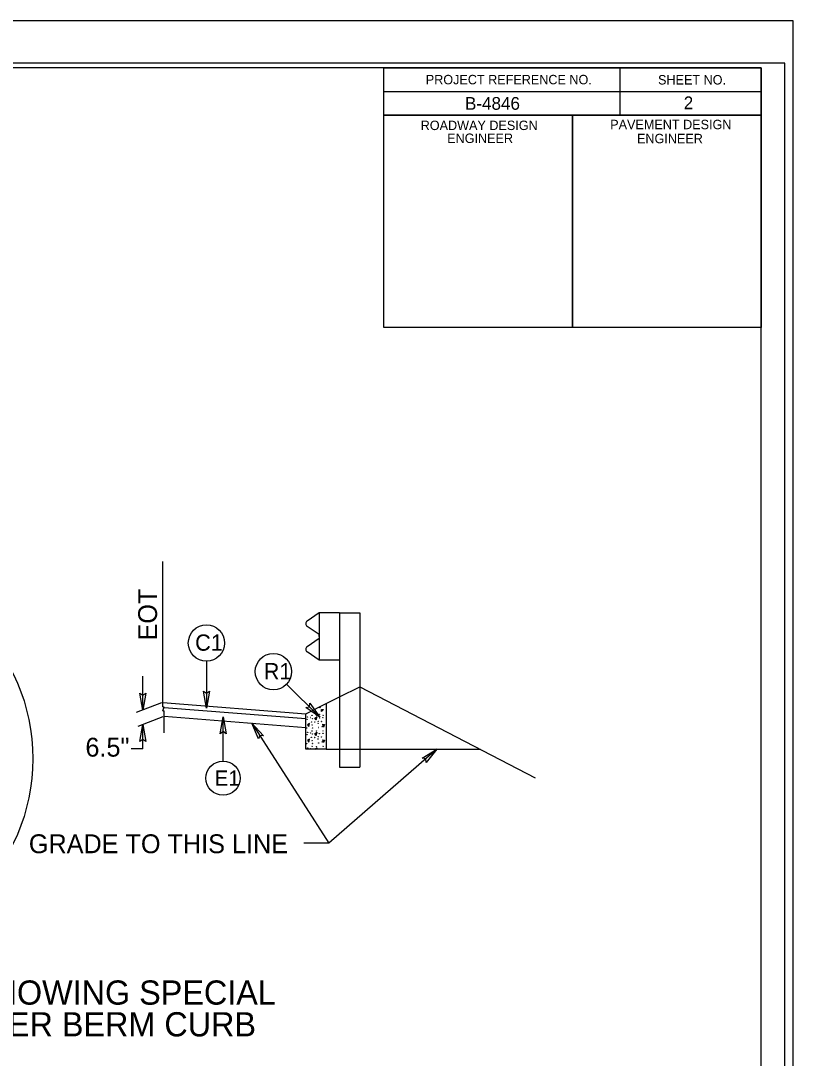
# Model space of a CAD drawing. Extents: x 1542177 to 1542464, y 45134 to 45344.
# Drawn here: x 1542327.96 to 1542360.73, y 45284.62 to 45328.62 of the extents above; entities that cross this region are included whole.
import ezdxf

# ---------------------------------------------------------------- set-up
doc = ezdxf.new("R2010")
doc.units = 0
for name, color, linetype in [('Default', 7, 'Continuous'), ('Old_Level_1', 7, 'Continuous'), ('Old_Level_2', 7, 'Continuous'), ('Sheet Cutting Line CELL', 7, 'Continuous'), ('Sheet Data Field CELL', 7, 'Continuous'), ('Sheet Plot Border Inside CELL', 7, 'Continuous'), ('Sheet Plot Border Outside CELL', 7, 'Continuous'), ('Sheet Typical CELL', 7, 'Continuous'), ('Typical Curb CELL', 7, 'Continuous'), ('Typical Guardrail CELL', 7, 'Continuous'), ('Typical ID Circle CELL', 7, 'Continuous'), ('Typical Terminator CELL', 7, 'Continuous'), ('Typical Text ID Circle CELL', 7, 'Continuous')]:
    doc.layers.add(name, color=color, linetype=linetype)

msp = doc.modelspace()

# ---------------------------------------------------------------- linework, layer by layer
at = {"layer": 'Default'}
for p, q in [((1542333.987, 45299.521), (1542333.987, 45305.678)), ((1542333.133, 45299.378), (1542333.133, 45300.813)), ((1542342.338, 45300.372), (1542349.785, 45296.513)), ((1542333.928, 45299.687), (1542332.859, 45299.272)), ((1542333.987, 45299.71), (1542340.051, 45299.229)), ((1542333.987, 45299.521), (1542334.045, 45299.521)), ((1542333.987, 45299.35), (1542334.045, 45299.521)), ((1542333.987, 45299.35), (1542334.045, 45299.35)), ((1542334.037, 45299.498), (1542340.051, 45299.021)), ((1542334.045, 45298.421), (1542334.045, 45299.35)), ((1542333.986, 45299.1), (1542332.917, 45298.684)), ((1542334.045, 45299.123), (1542340.051, 45298.646)), ((1542333.133, 45297.738), (1542333.133, 45298.768)), ((1542333.133, 45297.738), (1542332.644, 45297.738)), ((1542340.914, 45297.718), (1542347.46, 45297.718))]:
    msp.add_line(p, q, dxfattribs=at)
for points in [[(1542333.257, 45300.098), (1542333.133, 45299.378), (1542333.005, 45300.102), (1542333.133, 45300.01)], [(1542333.009, 45298.048), (1542333.133, 45298.768), (1542333.261, 45298.044), (1542333.133, 45298.136)]]:
    msp.add_lwpolyline(points, close=True, dxfattribs=at)
at = {"layer": 'Old_Level_2'}
for points in [[(1542337.754, 45298.828), (1542341.027, 45293.738), (1542339.965, 45293.737)], [(1542345.609, 45297.718), (1542341.027, 45293.738), (1542339.965, 45293.737)]]:
    msp.add_lwpolyline(points, dxfattribs=at)
at = {"layer": 'Sheet Cutting Line CELL'}
msp.add_line((1542360.727, 45328.616), (1542226.007, 45328.616), dxfattribs=at)
at = {"layer": 'Sheet Plot Border Inside CELL'}
msp.add_lwpolyline([(1542360.367, 45326.82), (1542227.047, 45326.82), (1542227.047, 45242.412), (1542360.367, 45242.412)], close=True, dxfattribs=at)
at = {"layer": 'Sheet Plot Border Outside CELL'}
for points in [[(1542360.727, 45328.616), (1542226.007, 45328.616), (1542226.007, 45240.616), (1542360.727, 45240.616)], [(1542360.727, 45328.615), (1542226.007, 45328.615), (1542226.007, 45240.616), (1542360.727, 45240.616)]]:
    msp.add_lwpolyline(points, close=True, dxfattribs=at)
at = {"layer": 'Sheet Typical CELL'}
for p, q in [((1542353.367, 45326.612), (1542353.367, 45324.612)), ((1542343.363, 45325.612), (1542359.367, 45325.612)), ((1542351.367, 45324.612), (1542351.367, 45315.616))]:
    msp.add_line(p, q, dxfattribs=at)
for points in [[(1542359.367, 45326.616), (1542239.367, 45326.616), (1542239.367, 45242.616), (1542359.367, 45242.616)], [(1542343.363, 45326.616), (1542359.367, 45326.616), (1542359.367, 45324.612), (1542343.363, 45324.612)], [(1542343.363, 45324.612), (1542351.367, 45324.612), (1542351.367, 45315.612), (1542343.363, 45315.612)], [(1542351.367, 45324.612), (1542359.367, 45324.612), (1542359.367, 45315.612), (1542351.367, 45315.612)]]:
    msp.add_lwpolyline(points, close=True, dxfattribs=at)
at = {"layer": 'Typical Curb CELL'}
for p, q in [((1542341.475, 45299.94), (1542342.338, 45300.372)), ((1542340.914, 45299.66), (1542341.475, 45299.94)), ((1542340.051, 45299.229), (1542340.914, 45299.66)), ((1542340.711, 45299.401), (1542340.797, 45299.401)), ((1542340.716, 45299.315), (1542340.711, 45299.401)), ((1542340.797, 45299.401), (1542340.716, 45299.315)), ((1542340.914, 45299.66), (1542340.914, 45297.718)), ((1542340.051, 45297.718), (1542340.051, 45299.229)), ((1542340.431, 45299.04), (1542340.513, 45299.099)), ((1542340.472, 45298.949), (1542340.431, 45299.04)), ((1542340.513, 45299.099), (1542340.472, 45298.949)), ((1542340.206, 45298.81), (1542340.116, 45298.76)), ((1542340.116, 45298.76), (1542340.174, 45298.679)), ((1542340.174, 45298.679), (1542340.206, 45298.81)), ((1542340.771, 45298.783), (1542340.843, 45298.769)), ((1542340.806, 45298.66), (1542340.771, 45298.783)), ((1542340.843, 45298.769), (1542340.806, 45298.66)), ((1542340.206, 45298.15), (1542340.116, 45298.1)), ((1542340.116, 45298.1), (1542340.174, 45298.019)), ((1542340.174, 45298.019), (1542340.206, 45298.15)), ((1542340.431, 45298.38), (1542340.513, 45298.439)), ((1542340.472, 45298.289), (1542340.431, 45298.38)), ((1542340.513, 45298.439), (1542340.472, 45298.289)), ((1542340.771, 45298.123), (1542340.843, 45298.109)), ((1542340.806, 45298), (1542340.771, 45298.123)), ((1542340.843, 45298.109), (1542340.806, 45298)), ((1542340.914, 45297.718), (1542340.051, 45297.718)), ((1542340.431, 45297.72), (1542340.513, 45297.779)), ((1542340.432, 45297.718), (1542340.431, 45297.72)), ((1542340.513, 45297.779), (1542340.496, 45297.718))]:
    msp.add_line(p, q, dxfattribs=at)
for centre in [(1542340.296, 45299.32), (1542340.648, 45299.487), (1542340.102, 45298.995), (1542340.124, 45299.094), (1542340.246, 45299.067), (1542340.287, 45298.882), (1542340.314, 45299.158), (1542340.336, 45299.022), (1542340.431, 45299.298), (1542340.431, 45298.878), (1542340.504, 45299.153), (1542340.58, 45298.909), (1542340.621, 45299.203), (1542340.626, 45299.04), (1542340.716, 45298.896), (1542340.775, 45299.054), (1542340.784, 45299.162), (1542340.088, 45298.62), (1542340.124, 45298.434), (1542340.314, 45298.498), (1542340.318, 45298.747), (1542340.332, 45298.625), (1542340.504, 45298.493), (1542340.567, 45298.814), (1542340.594, 45298.643), (1542340.739, 45298.683), (1542340.784, 45298.502), (1542340.102, 45298.335), (1542340.246, 45298.407), (1542340.287, 45298.222), (1542340.318, 45298.086), (1542340.336, 45298.362), (1542340.431, 45298.217), (1542340.567, 45298.154), (1542340.58, 45298.249), (1542340.626, 45298.38), (1542340.716, 45298.236), (1542340.739, 45298.023), (1542340.775, 45298.394), (1542340.088, 45297.96), (1542340.124, 45297.774), (1542340.246, 45297.747), (1542340.314, 45297.838), (1542340.332, 45297.965), (1542340.504, 45297.833), (1542340.594, 45297.982), (1542340.775, 45297.734), (1542340.784, 45297.842)]:
    msp.add_circle(centre, 0.00635, dxfattribs=at)
at = {"layer": 'Typical Guardrail CELL'}
for p, q in [((1542340.611, 45303.507), (1542340.109, 45303.154)), ((1542341.475, 45303.507), (1542340.611, 45303.507)), ((1542340.611, 45303.507), (1542340.611, 45301.494)), ((1542341.475, 45303.507), (1542341.475, 45299.94)), ((1542341.475, 45303.507), (1542342.338, 45303.507)), ((1542342.338, 45303.507), (1542342.338, 45300.372)), ((1542340.611, 45302.581), (1542340.109, 45302.933)), ((1542340.611, 45302.419), (1542340.109, 45302.067)), ((1542340.611, 45302.5), (1542340.611, 45302.581)), ((1542340.611, 45302.5), (1542340.611, 45302.419)), ((1542340.611, 45301.494), (1542340.109, 45301.846)), ((1542341.475, 45301.494), (1542340.611, 45301.494)), ((1542342.338, 45300.372), (1542342.338, 45296.967)), ((1542341.475, 45299.94), (1542341.475, 45296.967)), ((1542341.475, 45296.967), (1542342.338, 45296.967))]:
    msp.add_line(p, q, dxfattribs=at)
for centre, start, end in [((1542340.186, 45303.044), 125.003, 235.0112), ((1542340.186, 45301.956), 125.0059, 235.0366)]:
    msp.add_arc(centre, 0.135, start, end, dxfattribs=at)
at = {"layer": 'Typical ID Circle CELL'}
for p, q in [((1542335.834, 45301.455), (1542335.834, 45299.467)), ((1542339.224, 45300.475), (1542340.648, 45299.087)), ((1542336.538, 45297.219), (1542336.538, 45299.093))]:
    msp.add_line(p, q, dxfattribs=at)
for centre, radius in [((1542320.225, 45297.318), 8.241), ((1542335.834, 45302.225), 0.769), ((1542338.674, 45301.012), 0.769), ((1542336.538, 45296.494), 0.725)]:
    msp.add_circle(centre, radius, dxfattribs=at)
at = {"layer": 'Typical Terminator CELL'}
for points in [[(1542335.957, 45300.179), (1542335.834, 45299.467), (1542335.708, 45300.183), (1542335.834, 45300.092)], [(1542340.223, 45299.672), (1542340.648, 45299.087), (1542340.046, 45299.496), (1542340.2, 45299.523)], [(1542336.416, 45298.38), (1542336.538, 45299.093), (1542336.665, 45298.376), (1542336.538, 45298.467)], [(1542338.036, 45298.163), (1542337.754, 45298.828), (1542338.248, 45298.294), (1542338.092, 45298.302)], [(1542344.991, 45297.344), (1542345.609, 45297.718), (1542345.151, 45297.153), (1542345.137, 45297.308)]]:
    msp.add_lwpolyline(points, close=True, dxfattribs=at)

# ---------------------------------------------------------------- texts
at = {"layer": 'Default'}
msp.add_text('EOT', height=0.8, rotation=90, dxfattribs=at).set_placement((1542333.739, 45302.332))
for s, height, p in [('6.5"', 0.8, (1542330.701, 45297.408)), ('DETAIL SHOWING SPECIAL', 1.02627, (1542320.704, 45286.889)), ('SHOULDER BERM CURB', 1.02627, (1542321.695, 45285.543))]:
    msp.add_text(s, height=height, dxfattribs=at).set_placement(p)
at = {"layer": 'Old_Level_1'}
msp.add_text('GRADE TO THIS LINE ', height=0.8, dxfattribs=at).set_placement((1542328.3, 45293.312))
at = {"layer": 'Sheet Data Field CELL'}
for s, p in [('B-4846', (1542346.804, 45324.84)), ('2', (1542356.081, 45324.864))]:
    msp.add_text(s, height=0.54, dxfattribs=at).set_placement(p)
at = {"layer": 'Sheet Typical CELL'}
for s, height, p in [('PROJECT REFERENCE NO.', 0.40001, (1542345.139, 45325.92)), ('SHEET NO.', 0.4, (1542354.991, 45325.912)), ('PAVEMENT DESIGN', 0.40001, (1542352.963, 45324.016)), ('ROADWAY DESIGN', 0.40001, (1542344.923, 45323.98)), ('ENGINEER', 0.4, (1542346.047, 45323.432)), ('ENGINEER', 0.4, (1542354.099, 45323.42))]:
    msp.add_text(s, height=height, dxfattribs=at).set_placement(p)
at = {"layer": 'Typical Text ID Circle CELL'}
for s, height, rotation, p in [('C1', 0.6886, 360, (1542335.354, 45301.899)), ('R1', 0.6886, 0.0001, (1542338.264, 45300.687)), ('E1', 0.649, 360, (1542336.182, 45296.171))]:
    msp.add_text(s, height=height, rotation=rotation, dxfattribs=at).set_placement(p)

doc.saveas('drawing.dxf')
